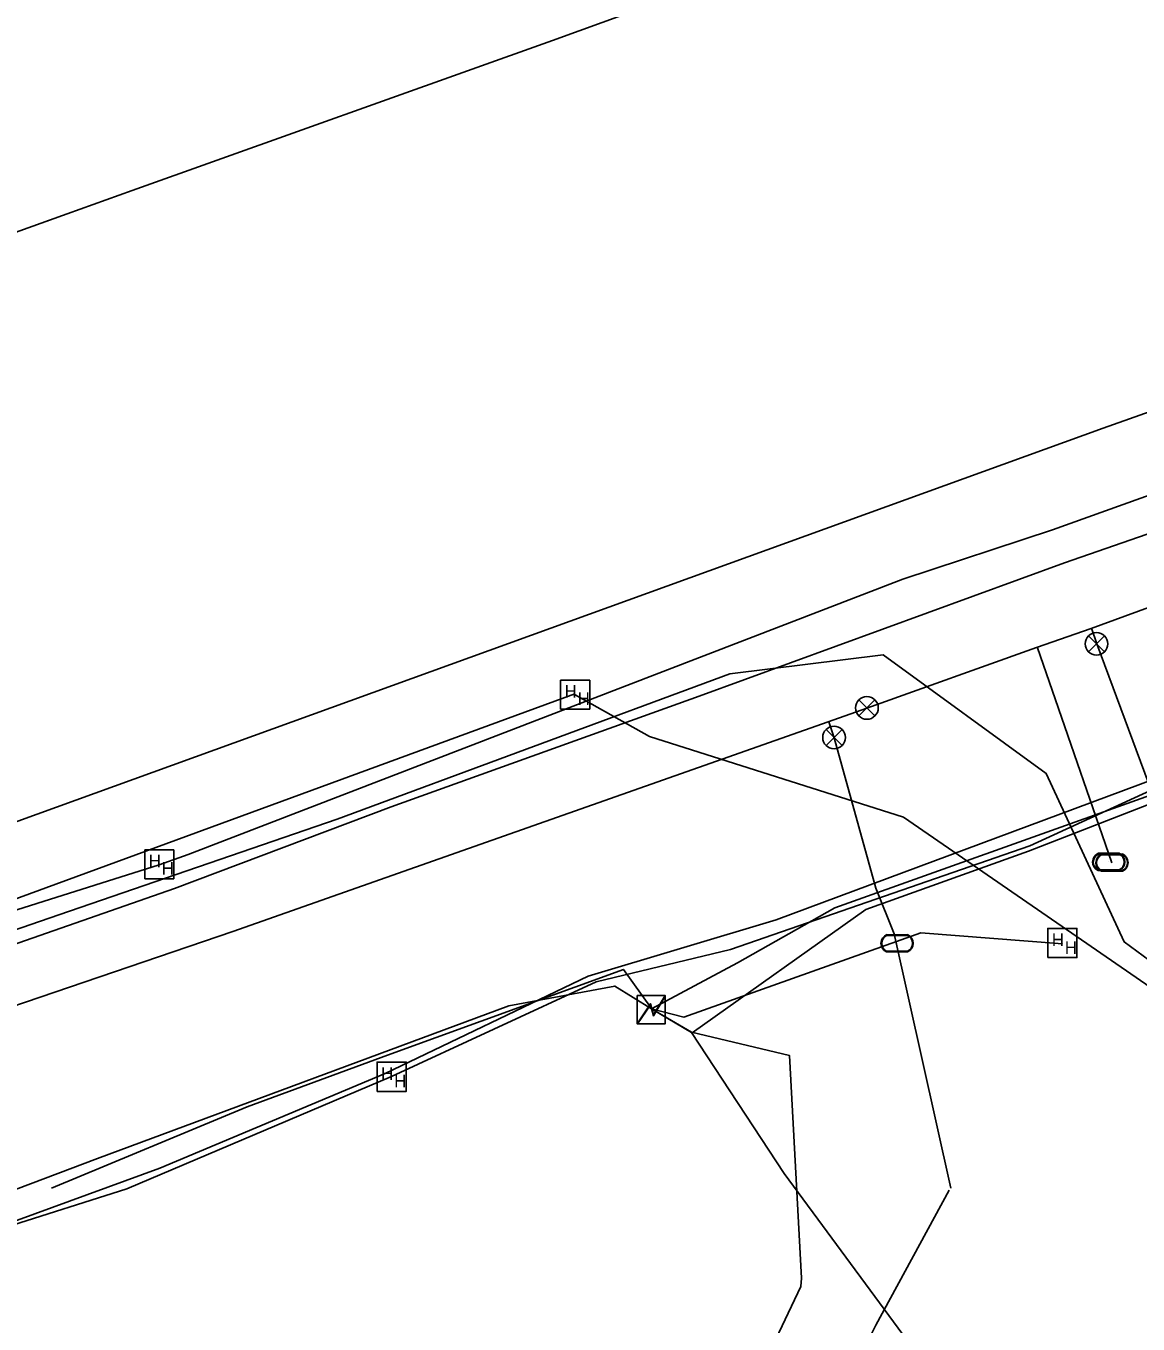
# Model space of a CAD drawing. Extents: x 2070721 to 2083039, y 729290 to 737883.
# Drawn here: x 2080544.7 to 2080763.5, y 734501.5 to 734756.8 of the extents above; entities that cross this region are included whole.
import ezdxf

# ---------------------------------------------------------------- set-up
doc = ezdxf.new("R2010")
doc.units = 0
for name, color, linetype in [('COGO Default Point Elevation', 7, 'Continuous'), ('Exist Utilities Power Pole CELL', 7, 'Continuous'), ('Exist Utilities Power Pole Cogo Elevation', 7, 'Continuous'), ('Exist Utilities Telephone UG Cable Cogo Point CELL', 7, 'Continuous'), ('Exist Utilities Telephone UG Cable SUE LOS C Cogo Elevation', 7, 'Continuous'), ('Exist Utilities Telephone UG Cable SUE LOS C Cogo Number', 7, 'Continuous'), ('Exist Utilities Telephone UG FO Cogo Point CELL', 7, 'Continuous'), ('Exist Utilities Telephone UG FO SUE LOS B Cogo Number', 7, 'Continuous'), ('Exist Utilities TV Pedestal Cogo Elevation', 7, 'Continuous'), ('Exist Utilities TV UG Cable Cogo Point CELL', 7, 'Continuous'), ('Exist Utilities TV UG Cable SUE LOS C Cogo Comment', 7, 'Continuous'), ('Exist Utilities TV UG Cable SUE LOS C Cogo Number', 7, 'Continuous'), ('Exist Utilities TV UG Cable SUE LOS C Cogo Point CELL', 7, 'Continuous'), ('Exist Utilities Water UG Line SUE LOS B Cogo Elevation', 7, 'Continuous'), ('Exist Utilities Water UG Line SUE LOS B Cogo Number', 7, 'Continuous')]:
    doc.layers.add(name, color=color, linetype=linetype)

msp = doc.modelspace()

# ---------------------------------------------------------------- linework, layer by layer
at = {"layer": 'COGO Default Point Elevation'}
for points in [[(2080756.89, 734636.83), (2080753.74, 734633.68), (2080755.32, 734635.25), (2080756.89, 734633.68), (2080753.74, 734636.83)], [(2080711.74, 734624.22), (2080708.58, 734621.08), (2080710.16, 734622.65), (2080711.74, 734621.08), (2080708.58, 734624.22)], [(2080705.27, 734618.41), (2080702.12, 734615.26), (2080703.69, 734616.83), (2080705.27, 734615.26), (2080702.12, 734618.41)]]:
    msp.add_lwpolyline(points, dxfattribs=at)
for centre in [(2080755.32, 734635.25), (2080710.16, 734622.65), (2080703.69, 734616.83)]:
    msp.add_circle(centre, 2.23, dxfattribs=at)
at = {"layer": 'Exist Utilities Power Pole CELL'}
msp.add_lwpolyline([(2080232.24, 734245.67), (2080237.5, 734254.36), (2080238.66, 734282.35), (2080245.75, 734323.83), (2080258.86, 734369.55), (2080269.86, 734398.57), (2080309.08, 734449.32), (2080323.63, 734464.88), (2080355.41, 734492.16), (2080379.52, 734509.8), (2080416.03, 734529.49), (2080502.71, 734562.3), (2080573.96, 734587.12), (2080616.57, 734603.22), (2080677.16, 734624.99), (2080749, 734651.22), (2080815.57, 734674.3), (2080861.11, 734690.56), (2080923.26, 734714.15), (2080934.26, 734720.97)], dxfattribs=at)
at = {"layer": 'Exist Utilities Power Pole Cogo Elevation'}
for points in [[(2080667.78, 734563.47), (2080684.69, 734572.51), (2080703.86, 734583.33), (2080803.07, 734618.73), (2080822.19, 734625.25), (2080887.34, 734649.65)], [(2080537.8, 734526.08), (2080558.84, 734534.05), (2080639.7, 734564.08), (2080660.56, 734567.92), (2080667.78, 734563.47)]]:
    msp.add_lwpolyline(points, dxfattribs=at)
at = {"layer": 'Exist Utilities Telephone UG Cable Cogo Point CELL'}
msp.add_line((2080616.68, 734550.11), (2080616.68, 734550.11), dxfattribs=at)
msp.add_lwpolyline([(2080613.8, 734547.23), (2080619.55, 734547.23), (2080619.55, 734552.98), (2080613.8, 734552.98), (2080613.8, 734547.23)], dxfattribs=at)
at = {"layer": 'Exist Utilities Telephone UG Cable SUE LOS C Cogo Elevation'}
msp.add_line((2080748.68, 734576.27), (2080748.68, 734576.27), dxfattribs=at)
msp.add_lwpolyline([(2080745.73, 734573.54), (2080751.48, 734573.54), (2080751.48, 734579.29), (2080745.73, 734579.29), (2080745.73, 734573.54)], dxfattribs=at)
at = {"layer": 'Exist Utilities Telephone UG Cable SUE LOS C Cogo Number'}
msp.add_line((2080667.78, 734563.47), (2080667.78, 734563.47), dxfattribs=at)
msp.add_lwpolyline([(2080664.94, 734566.08), (2080670.49, 734566.08), (2080670.49, 734560.53), (2080664.94, 734560.53)], close=True, dxfattribs=at)
for points in [[(2080664.94, 734560.53), (2080667.58, 734564.47), (2080668.21, 734562.26), (2080670.49, 734566.08)], [(2080665.01, 734560.53), (2080667.58, 734564.26), (2080668.17, 734562.08), (2080670.49, 734565.93)]]:
    msp.add_lwpolyline(points, dxfattribs=at)
at = {"layer": 'Exist Utilities Telephone UG FO Cogo Point CELL'}
for p, q in [((2080757.72, 734592.35), (2080757.72, 734592.35)), ((2080758.36, 734592.21), (2080758.36, 734592.21)), ((2080716.09, 734576.34), (2080716.09, 734576.34))]:
    msp.add_line(p, q, dxfattribs=at)
for points in [[(2080755.68, 734594.05), (2080759.76, 734594.05)], [(2080755.68, 734593.92), (2080759.76, 734593.92)], [(2080756.33, 734593.91), (2080760.4, 734593.91)], [(2080756.33, 734593.78), (2080760.4, 734593.78)], [(2080759.76, 734590.79), (2080755.66, 734590.79)], [(2080759.76, 734590.65), (2080755.66, 734590.65)], [(2080760.4, 734590.65), (2080756.3, 734590.65)], [(2080760.4, 734590.51), (2080756.3, 734590.51)], [(2080714.05, 734578.04), (2080718.13, 734578.04)], [(2080714.05, 734577.91), (2080718.13, 734577.91)], [(2080718.13, 734574.78), (2080714.03, 734574.78)], [(2080718.13, 734574.64), (2080714.03, 734574.64)]]:
    msp.add_lwpolyline(points, dxfattribs=at)
for centre, radius, start, end in [((2080756.41, 734592.35), 1.86, 113.178, 245.9794), ((2080756.42, 734592.35), 1.73, 115.3009, 243.7824), ((2080757.06, 734592.21), 1.86, 113.178, 245.9794), ((2080757.07, 734592.21), 1.73, 115.3009, 243.7824), ((2080759.01, 734592.35), 1.86, 293.6483, 66.3084), ((2080759.03, 734592.35), 1.73, 295.1272, 64.8728), ((2080759.66, 734592.22), 1.86, 293.6483, 66.3084), ((2080759.67, 734592.21), 1.73, 295.1272, 64.8728), ((2080714.78, 734576.34), 1.86, 113.178, 245.9794), ((2080714.79, 734576.34), 1.73, 115.3009, 243.7824), ((2080717.38, 734576.35), 1.86, 293.6483, 66.3084), ((2080717.39, 734576.34), 1.73, 295.1272, 64.8728)]:
    msp.add_arc(centre, radius, start, end, dxfattribs=at)
at = {"layer": 'Exist Utilities Telephone UG FO SUE LOS B Cogo Number'}
for p, q in [((2080649.9, 734628.12), (2080649.9, 734622.39)), ((2080655.63, 734628.12), (2080649.9, 734628.12)), ((2080655.63, 734622.39), (2080655.63, 734628.12)), ((2080652.77, 734625.25), (2080652.77, 734625.25)), ((2080649.9, 734622.39), (2080655.63, 734622.39)), ((2080568.1, 734594.76), (2080568.1, 734589.04)), ((2080573.82, 734594.76), (2080568.1, 734594.76)), ((2080573.82, 734589.04), (2080573.82, 734594.76)), ((2080570.96, 734591.9), (2080570.96, 734591.9)), ((2080568.1, 734589.04), (2080573.82, 734589.04))]:
    msp.add_line(p, q, dxfattribs=at)
at = {"layer": 'Exist Utilities TV Pedestal Cogo Elevation'}
for points in [[(2080357.06, 734003.27), (2080353.32, 734006.79), (2080296.63, 734072.2), (2080261.95, 734141.13), (2080251.22, 734185.42), (2080250, 734189.2), (2080244.12, 734248.6), (2080244.13, 734251.5), (2080244.63, 734259.68), (2080245.13, 734264.1), (2080254.44, 734320.44), (2080276.53, 734380.91), (2080391.41, 734503.18), (2080497.9, 734548.7), (2080500.72, 734549.83), (2080585.45, 734578.7), (2080702.53, 734619.89), (2080710.17, 734622.62), (2080743.51, 734634.52), (2080754.26, 734638.28), (2080902.52, 734692.58), (2081024.44, 734735.33)], [(2080754.33, 734638.34), (2080755.39, 734635.25), (2080768.66, 734599.39)], [(2080758.36, 734592.21), (2080746.58, 734626.15), (2080743.73, 734634.44)], [(2080702.68, 734619.94), (2080703.69, 734616.8), (2080711.9, 734587.21), (2080715.5, 734578.22), (2080726.68, 734528.21)], [(2080710.45, 734498.38), (2080711.94, 734501.21), (2080726.31, 734527.8)]]:
    msp.add_lwpolyline(points, dxfattribs=at)
at = {"layer": 'Exist Utilities TV UG Cable Cogo Point CELL'}
for points in [[(2080527.18, 734594.58), (2080756.63, 734677.7), (2080975.53, 734755.33), (2081114.85, 734806.49), (2081251.31, 734880.3), (2081357.91, 734934.96), (2081407.46, 734955.63), (2081557.34, 735013.56), (2081611.19, 735031.21), (2081670.8, 735036.79), (2081727.82, 735033.26), (2081796.62, 735020.83), (2081876.61, 734998.57), (2081913.61, 734982.12), (2081940.08, 734960.79), (2081955.36, 734908.6), (2081940.34, 734844.38), (2081917.15, 734795.51)], [(2080392.43, 734459.45), (2080392.18, 734455.98), (2080369.79, 734491.21), (2080371.64, 734506.16), (2080398.8, 734522.93), (2080423.1, 734536.76), (2080488.87, 734560.43), (2080551.19, 734581.93), (2080605.97, 734600.8), (2080683.17, 734629.37), (2080713.38, 734633.09), (2080745.42, 734609.78), (2080760.77, 734576.63), (2080781.91, 734561.06), (2080789.84, 734547.84), (2080795.45, 734523.96), (2080798.47, 734502.81), (2080795.45, 734476.11), (2080787.39, 734456.13)]]:
    msp.add_lwpolyline(points, dxfattribs=at)
at = {"layer": 'Exist Utilities TV UG Cable SUE LOS C Cogo Comment'}
for points in [[(2080667.78, 734563.47), (2080675.81, 734558.73), (2080709.93, 734583.03), (2080741.96, 734594.47), (2080777.33, 734608.24), (2080817.29, 734620.64)], [(2080748.6, 734576.24), (2080720.77, 734578.39), (2080674.14, 734561.84), (2080667.78, 734563.47)], [(2080549.75, 734528.17), (2080588.23, 734544.21), (2080615.83, 734554.35), (2080662.27, 734571.22), (2080667.81, 734563.54)], [(2080697.31, 734510.51), (2080694.95, 734554.25), (2080675.63, 734558.89), (2080667.78, 734563.47)], [(2080667.78, 734563.47), (2080675.67, 734558.83), (2080693.85, 734531.06), (2080722.9, 734491.66), (2080736.23, 734470.41), (2080750.76, 734434.85), (2080756.8, 734404.17), (2080750.61, 734393.55), (2080741.92, 734388.6), (2080737.52, 734385.1)], [(2080697.31, 734510.51), (2080697.15, 734508.83), (2080681.13, 734475.16), (2080665.04, 734428.4), (2080656.55, 734378.37), (2080659.43, 734370.95), (2080688.68, 734366.16), (2080705.41, 734368.17), (2080719.63, 734366.67), (2080730.12, 734371.17), (2080737.52, 734377.9), (2080737.52, 734385.1)]]:
    msp.add_lwpolyline(points, dxfattribs=at)
at = {"layer": 'Exist Utilities TV UG Cable SUE LOS C Cogo Number'}
msp.add_lwpolyline([(2080540.63, 734520.42), (2080564.59, 734528.02), (2080616.67, 734550.17), (2080656.9, 734568.75), (2080683.34, 734575.14), (2080742.18, 734595.53), (2080780.96, 734613.32), (2080816.71, 734626.79), (2080878.8, 734650.08), (2080920.95, 734664.77), (2080961.27, 734680.22)], dxfattribs=at)
at = {"layer": 'Exist Utilities TV UG Cable SUE LOS C Cogo Point CELL'}
for points in [[(2079745.48, 734481.51), (2079801.23, 734497.35), (2079872.83, 734508.05), (2079949.65, 734523.37), (2080020.61, 734534.5), (2080089.55, 734553.89), (2080188.62, 734588.57), (2080251.31, 734612.62), (2080291.78, 734621.68), (2080331.66, 734636.74), (2080409.13, 734669.6), (2080483.75, 734695.04), (2080565.61, 734724.43), (2080648.3, 734753.97), (2080723.36, 734781.19), (2080819.84, 734816.74), (2080898.17, 734842.61), (2080939.09, 734839.81)], [(2080717.24, 734648.01), (2080746.66, 734657.69), (2080787.43, 734672.3), (2080932.78, 734725.13), (2080966.26, 734736.59)], [(2080235.11, 734249.36), (2080234.94, 734252.48), (2080236.58, 734281.87), (2080244.62, 734323.58), (2080257.8, 734369.84), (2080268.59, 734399.28), (2080285.42, 734425.78), (2080306.49, 734446.52), (2080318.99, 734464.89), (2080332.07, 734479.26), (2080365.28, 734504.24), (2080415, 734536.31), (2080432.75, 734546.34), (2080471.85, 734557.5), (2080502.31, 734568.65), (2080534.18, 734580.2), (2080570.94, 734591.77), (2080576.66, 734593.81), (2080717.24, 734648.01)], [(2080228.28, 734243.43), (2080230.55, 734282.39), (2080237.1, 734324.84), (2080265.61, 734400.42), (2080300.19, 734451.55), (2080329.83, 734482.91), (2080380.99, 734522.11), (2080413.6, 734539.64), (2080433.63, 734544.47), (2080470.56, 734559.5), (2080533.58, 734581.77), (2080652.68, 734625.4)]]:
    msp.add_lwpolyline(points, dxfattribs=at)
at = {"layer": 'Exist Utilities Water UG Line SUE LOS B Cogo Elevation'}
for points in [[(2080615.4, 734550.71), (2080655.3, 734569.86), (2080692.31, 734580.99), (2080772.95, 734610.98), (2080780.99, 734613.36)], [(2080376.9, 734455.01), (2080393.72, 734461.75), (2080438.63, 734479.28), (2080476.05, 734497.46), (2080571.1, 734532.14), (2080615.4, 734550.71)]]:
    msp.add_lwpolyline(points, dxfattribs=at)
at = {"layer": 'Exist Utilities Water UG Line SUE LOS B Cogo Number'}
msp.add_lwpolyline([(2080652.77, 734625.25), (2080667.42, 734617.06), (2080717.34, 734601.19), (2080782.55, 734556.25), (2080795.25, 734516.63), (2080795.25, 734490.1), (2080786.86, 734462.06), (2080786.86, 734458.84)], dxfattribs=at)

# ---------------------------------------------------------------- texts
at = {"layer": 'Exist Utilities Telephone UG Cable Cogo Point CELL'}
for p in [(2080614.59, 734549.46), (2080617.16, 734548)]:
    msp.add_text('H', height=2.5, dxfattribs=at).set_placement(p)
at = {"layer": 'Exist Utilities Telephone UG Cable SUE LOS C Cogo Elevation'}
for p in [(2080746.52, 734575.79), (2080749.09, 734574.27)]:
    msp.add_text('H', height=2.5, dxfattribs=at).set_placement(p)
at = {"layer": 'Exist Utilities Telephone UG FO SUE LOS B Cogo Number'}
for p in [(2080650.68, 734624.66), (2080653.25, 734623.2), (2080568.88, 734591.31), (2080571.45, 734589.84)]:
    msp.add_text('H', height=2.5, dxfattribs=at).set_placement(p)

doc.saveas('drawing.dxf')
